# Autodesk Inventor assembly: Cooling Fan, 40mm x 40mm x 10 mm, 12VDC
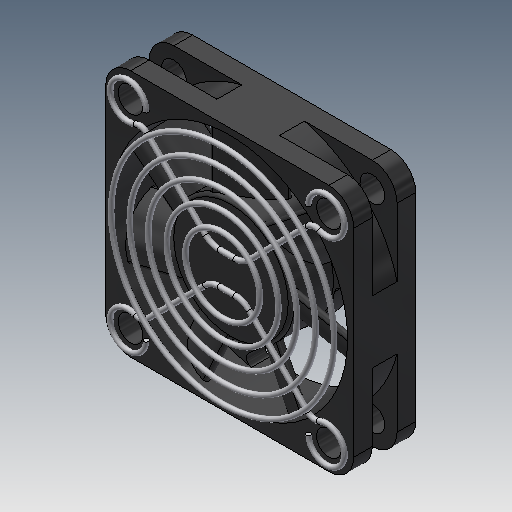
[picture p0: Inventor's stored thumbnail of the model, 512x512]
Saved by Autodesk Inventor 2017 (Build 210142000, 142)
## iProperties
Created: 2005-12
Part Number: Cooling Fan, 40mm x 40mm x 10 mm, 12VDC
Document SubType Name: Assembly
Designer: DanielSeverino
Author: DanielSeverino
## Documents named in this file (3)
- C:\Users\DanielSeverino\Desktop\01\Cooling Fan, 40mm x 40mm x 10 mm, 12VDC.iam
- C:\Users\DanielSeverino\Desktop\01\Cooling Fan, 40mm x 40mm x 10 mm, 12VDC.ipt
- C:\Users\DanielSeverino\Desktop\01\Fan Guard, 40mm.ipt
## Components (2 placed, 2 different names)
1. Cooling Fan, 40mm x 40mm x 10 mm, 12VDC:1
2. Fan Guard, 40mm:1
